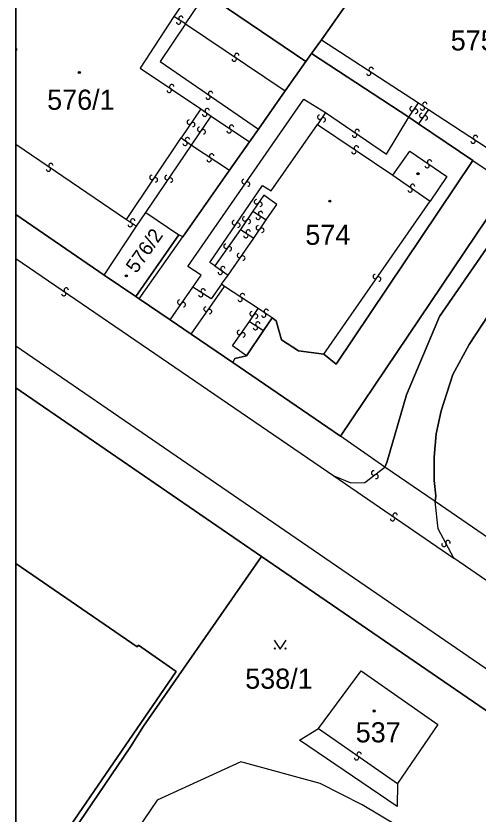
# Model space of a CAD drawing. Extents: x -600309 to -598967, y -1161267 to -1160292.
# Drawn here: x -600308.5 to -600269.6, y -1160535.7 to -1160468.5 of the extents above; entities that cross this region are included whole.
import ezdxf

# ---------------------------------------------------------------- set-up
doc = ezdxf.new("R2010")
doc.units = 0
for name, color, linetype in [('Level 1', 7, 'Continuous'), ('Level 13', 7, 'Continuous'), ('Level 3', 7, 'Continuous'), ('Level 4', 7, 'Continuous'), ('Level 5', 7, 'Continuous'), ('Level 60', 7, 'Continuous'), ('Vrstva 60', 7, 'Continuous'), ('Vrstva 63', 7, 'Continuous')]:
    doc.layers.add(name, color=color, linetype=linetype)

msp = doc.modelspace()

# ---------------------------------------------------------------- linework, layer by layer
at = {"layer": 'Level 1'}
for p, q in [((-600308.541, -1160485.2), (-600301.11, -1160490.31)), ((-600308.541, -1160499.81), (-600287.84, -1160514.02))]:
    msp.add_line(p, q, dxfattribs=at)
for points in [[(-600282.78, -1160470.49), (-600273.4, -1160457.1)], [(-600292.53, -1160466.58), (-600284.1, -1160472.3)], [(-600283.63, -1160471.64), (-600282.78, -1160470.49)], [(-600284.1, -1160472.3), (-600283.63, -1160471.64)], [(-600275.42, -1160477.01), (-600283.63, -1160471.64)], [(-600284.1, -1160472.3), (-600285.83, -1160474.79)], [(-600242.67, -1160473.81), (-600246.89, -1160473.4), (-600249.82, -1160473.65), (-600252.59, -1160474.29), (-600255.09, -1160475.12), (-600257.31, -1160476.17), (-600260.33, -1160477.98), (-600262.97, -1160480.2), (-600264.66, -1160481.97), (-600272.84, -1160493.8), (-600275.6, -1160500.4), (-600277.27, -1160506.1), (-600277.44, -1160506.49)], [(-600285.83, -1160474.79), (-600288.09, -1160478.01)], [(-600275.42, -1160477.01), (-600274.59, -1160477.56)], [(-600270.03, -1160480.64), (-600274.59, -1160477.56)], [(-600288.09, -1160478.01), (-600288.84, -1160479.08)], [(-600288.84, -1160479.08), (-600290.54, -1160481.48)], [(-600270.03, -1160480.64), (-600281.53, -1160497.81), (-600282.59, -1160496.99)], [(-600290.54, -1160481.48), (-600294.47, -1160487.08)], [(-600281.18, -1160503.89), (-600266.93, -1160482.72)], [(-600298.38, -1160486.2), (-600297.59, -1160485.05)], [(-600297.59, -1160485.05), (-600294.81, -1160486.92)], [(-600301.11, -1160490.31), (-600298.38, -1160486.2)], [(-600298.44, -1160492.13), (-600294.81, -1160486.92)], [(-600298.15, -1160492.32), (-600294.47, -1160487.08)], [(-600264.44, -1160487.2), (-600270.32, -1160496.15), (-600271.69, -1160498.68), (-600272.7, -1160501.74), (-600273.1, -1160503.69), (-600273.29, -1160505.66), (-600273.28, -1160507.64), (-600273.15, -1160508.93), (-600273.18, -1160509.41)], [(-600301.11, -1160490.31), (-600298.44, -1160492.13)], [(-600298.44, -1160492.13), (-600298.15, -1160492.32)], [(-600298.15, -1160492.32), (-600295.54, -1160494.09)], [(-600287.66, -1160494.97), (-600286.95, -1160493.92)], [(-600286.95, -1160493.92), (-600286.6, -1160494.17), (-600286.14, -1160495.77), (-600284.73, -1160496.71), (-600282.59, -1160496.99)], [(-600295.54, -1160494.09), (-600293.77, -1160495.29)], [(-600293.77, -1160495.29), (-600290.24, -1160497.67)], [(-600289.11, -1160497.13), (-600287.66, -1160494.97)], [(-600290.24, -1160497.67), (-600290.08, -1160497.34), (-600289.11, -1160497.13)], [(-600290.24, -1160497.67), (-600281.18, -1160503.89)], [(-600277.44, -1160506.49), (-600281.18, -1160503.89)], [(-600273.18, -1160509.41), (-600277.44, -1160506.49)], [(-600236.23, -1160534.79), (-600273.18, -1160509.41)], [(-600308.541, -1160544.31), (-600298.89, -1160530.07), (-600297.78, -1160528.33), (-600287.84, -1160514.02)], [(-600261.56, -1160532.05), (-600287.84, -1160514.02)], [(-600308.541, -1160514.629), (-600298.31, -1160521.66), (-600298.2, -1160521.51), (-600295.03, -1160523.73), (-600308.541, -1160543.415)], [(-600283.03, -1160528.54), (-600279.44, -1160523.67), (-600272.96, -1160528.19), (-600276.38, -1160533.16)], [(-600276.38, -1160533.16), (-600276.4, -1160535.11), (-600284.62, -1160529.5), (-600283.03, -1160528.54)]]:
    msp.add_lwpolyline(points, dxfattribs=at)
at = {"layer": 'Level 13'}
for centre, start, end in [((-600294.829, -1160468.976), 185.47258, 57.57058), ((-600294.632, -1160468.664), 5.25812, 237.84812), ((-600289.925, -1160471.808), 3.38499, 235.48298), ((-600290.134, -1160472.112), 183.17053, 55.76053), ((-600278.588, -1160472.986), 4.41531, 236.51331), ((-600278.791, -1160473.294), 184.20085, 56.79085), ((-600295.406, -1160474.428), 3.55374, 235.65174), ((-600295.613, -1160474.732), 183.33928, 55.92928), ((-600292.134, -1160475.009), 2.89352, 234.99151), ((-600292.345, -1160475.311), 182.67906, 55.26906), ((-600274.068, -1160475.927), 4.15748, 236.25548), ((-600292.412, -1160476.451), 1.8974, 233.9954), ((-600275.151, -1160476.294), 92.92454, 325.02254), ((-600274.849, -1160476.505), 272.71009, 145.30009), ((-600274.271, -1160476.234), 183.94303, 56.53303), ((-600292.627, -1160476.749), 181.68294, 54.27294), ((-600282.932, -1160477.007), 93.33619, 325.92619), ((-600282.628, -1160477.214), 273.55065, 145.64864), ((-600274.321, -1160476.854), 92.38932, 324.97932), ((-600274.019, -1160477.067), 272.60378, 144.70178), ((-600293.932, -1160477.416), 92.98719, 325.57719), ((-600293.628, -1160477.625), 273.20165, 145.29965), ((-600290.356, -1160477.848), 3.56041, 235.65841), ((-600293.052, -1160478.025), 93.30502, 325.40301), ((-600292.748, -1160478.234), 273.09056, 145.68056), ((-600290.563, -1160478.152), 183.34596, 55.93596), ((-600279.984, -1160478.512), 182.85408, 55.44408), ((-600279.775, -1160478.209), 3.06853, 235.16653), ((-600294.284, -1160479.202), 183.17211, 55.76211), ((-600294.075, -1160478.898), 3.38657, 235.48456), ((-600270.001, -1160479.024), 184.03787, 56.62787), ((-600269.798, -1160478.716), 4.25233, 236.35032), ((-600280.044, -1160479.902), 183.13582, 55.72582), ((-600279.835, -1160479.598), 3.35028, 235.44828), ((-600292.243, -1160480.573), 183.42678, 56.01678), ((-600292.036, -1160480.268), 3.64124, 235.73923), ((-600305.595, -1160481.078), 3.1643, 235.2623), ((-600273.874, -1160481.092), 182.83723, 55.42723), ((-600273.665, -1160480.789), 3.05168, 235.14968), ((-600305.804, -1160481.382), 182.94985, 55.53985), ((-600297.082, -1160482.076), 93.5098, 325.6078), ((-600296.778, -1160482.283), 273.29534, 145.88534), ((-600295.812, -1160482.095), 93.26715, 325.36515), ((-600295.508, -1160482.304), 273.0527, 145.6427), ((-600289.31, -1160482.433), 92.58042, 324.67842), ((-600289.009, -1160482.646), 272.36597, 144.95597), ((-600275.306, -1160483.14), 182.22734, 54.81734), ((-600275.093, -1160482.84), 2.4418, 234.53979), ((-600288.261, -1160484.135), 92.68606, 325.27606), ((-600287.959, -1160484.346), 272.90052, 144.99852), ((-600287.908, -1160485.127), 4.15326, 236.25126), ((-600298.904, -1160486.062), 182.85049, 55.44049), ((-600298.695, -1160485.759), 3.06494, 235.16294), ((-600290.131, -1160485.894), 92.9131, 325.01109), ((-600289.252, -1160485.576), 93.04381, 325.63381), ((-600288.948, -1160485.785), 273.25826, 145.35626), ((-600288.112, -1160485.434), 183.9388, 56.5288), ((-600289.829, -1160486.105), 272.69864, 145.28864), ((-600288.947, -1160486.687), 4.03203, 236.13002), ((-600288.113, -1160486.326), 93.68267, 325.78066), ((-600287.807, -1160486.533), 273.46821, 146.05821), ((-600289.152, -1160486.993), 183.81757, 56.40757), ((-600290.84, -1160487.884), 92.1914, 324.7814), ((-600290.54, -1160488.097), 272.40585, 144.50385), ((-600289.711, -1160488.663), 92.59145, 324.68945), ((-600289.409, -1160488.876), 272.37699, 144.96699), ((-600291.308, -1160490.069), 181.6206, 54.2106), ((-600291.091, -1160489.771), 1.83506, 233.93305), ((-600278.25, -1160490.433), 92.55996, 324.65796), ((-600277.949, -1160490.646), 272.3455, 144.9355), ((-600304.505, -1160491.881), 182.80285, 55.39285), ((-600304.295, -1160491.579), 3.01731, 235.1153), ((-600292.96, -1160491.965), 184.90154, 56.99954), ((-600292.761, -1160491.655), 4.68709, 237.27709), ((-600289.438, -1160492.047), 3.88778, 236.47778), ((-600294.731, -1160492.594), 92.78528, 324.88328), ((-600294.429, -1160492.805), 272.57082, 145.16082), ((-600289.643, -1160492.353), 184.10224, 56.20023), ((-600292.52, -1160493.173), 92.51485, 324.61285), ((-600292.219, -1160493.386), 272.30039, 144.89039), ((-600287.437, -1160493.377), 3.46821, 236.05821), ((-600288.632, -1160493.576), 93.43623, 325.53423), ((-600288.328, -1160493.783), 273.22178, 145.81178), ((-600287.644, -1160493.683), 183.68267, 55.78066), ((-600288.35, -1160494.744), 184.374, 56.964), ((-600288.149, -1160494.436), 4.58845, 236.68645), ((-600289.701, -1160495.144), 92.73519, 324.83319), ((-600289.399, -1160495.355), 272.52074, 145.11074), ((-600278.392, -1160506.993), 75.15371, 307.25171), ((-600278.168, -1160507.286), 254.93926, 127.52926), ((-600276.785, -1160510.851), 182.62569, 55.21569), ((-600276.574, -1160510.549), 2.84014, 234.93814), ((-600272.117, -1160512.855), 334.91682, 207.50682), ((-600272.444, -1160513.024), 155.13128, 27.22927), ((-600279.816, -1160531.001), 182.36914, 54.95914), ((-600279.603, -1160530.7), 2.5836, 234.6816)]:
    msp.add_arc(centre, 0.184, start, end, dxfattribs=at)
at = {"layer": 'Level 3'}
for p, q in [((-600308.541, -1160479.29), (-600299.23, -1160485.62)), ((-600308.541, -1160488.903), (-600281.73, -1160507.23)), ((-600308.541, -1160496.264), (-600187.53, -1160579.36))]:
    msp.add_line(p, q, dxfattribs=at)
for points in [[(-600293.48, -1160465.96), (-600295.22, -1160468.51)], [(-600294.24, -1160469.12), (-600292.53, -1160466.58)], [(-600295.22, -1160468.51), (-600298.07, -1160472.86), (-600292.95, -1160476.29)], [(-600294.24, -1160469.12), (-600295.22, -1160468.51)], [(-600294.24, -1160469.12), (-600296.39, -1160472.31), (-600288.09, -1160478.01)], [(-600294.24, -1160469.12), (-600285.83, -1160474.79)], [(-600282.78, -1160470.49), (-600274.59, -1160475.8)], [(-600308.541, -1160471.445), (-600308.43, -1160471.28), (-600308.541, -1160471.202)], [(-600293.63, -1160491.32), (-600292.93, -1160490.33), (-600294.06, -1160489.58), (-600284.27, -1160475.49), (-600282.44, -1160476.61)], [(-600275.42, -1160477.01), (-600274.59, -1160475.8)], [(-600274.59, -1160475.8), (-600273.75, -1160476.35)], [(-600292.95, -1160476.29), (-600294.62, -1160478.75)], [(-600292.95, -1160476.29), (-600292.08, -1160476.91)], [(-600273.75, -1160476.35), (-600274.59, -1160477.56)], [(-600273.75, -1160476.35), (-600266.04, -1160481.38)], [(-600293.73, -1160479.35), (-600292.08, -1160476.91)], [(-600292.08, -1160476.91), (-600288.84, -1160479.08)], [(-600282.44, -1160476.61), (-600283.11, -1160477.61)], [(-600282.44, -1160476.61), (-600277.31, -1160480.11), (-600275.42, -1160477.01)], [(-600291.76, -1160489.52), (-600292.2, -1160489.24), (-600287.76, -1160482.77), (-600287.01, -1160483.21), (-600283.11, -1160477.61)], [(-600283.11, -1160477.61), (-600276.77, -1160481.89)], [(-600299.23, -1160485.62), (-600294.62, -1160478.75)], [(-600294.62, -1160478.75), (-600293.73, -1160479.35)], [(-600297.59, -1160485.05), (-600293.73, -1160479.35)], [(-600293.73, -1160479.35), (-600290.54, -1160481.48)], [(-600276.77, -1160481.89), (-600275.33, -1160479.87), (-600272.21, -1160482), (-600273.62, -1160484.09)], [(-600270.03, -1160480.64), (-600266.93, -1160482.72)], [(-600276.77, -1160481.89), (-600273.62, -1160484.09)], [(-600287.44, -1160485.65), (-600286.53, -1160484.35), (-600287.65, -1160483.57), (-600288.57, -1160484.91)], [(-600282.59, -1160496.99), (-600273.62, -1160484.09)], [(-600288.57, -1160484.91), (-600289.62, -1160486.46)], [(-600288.57, -1160484.91), (-600287.44, -1160485.65)], [(-600299.23, -1160485.62), (-600298.38, -1160486.2)], [(-600288.48, -1160487.21), (-600287.44, -1160485.65)], [(-600289.62, -1160486.46), (-600291.76, -1160489.52)], [(-600289.62, -1160486.46), (-600288.48, -1160487.21)], [(-600294.47, -1160487.08), (-600294.81, -1160486.92)], [(-600290.64, -1160490.32), (-600288.48, -1160487.21)], [(-600291.76, -1160489.52), (-600290.64, -1160490.32)], [(-600291.2, -1160491.07), (-600290.64, -1160490.32)], [(-600293.77, -1160495.29), (-600290.97, -1160491.27)], [(-600291.2, -1160491.07), (-600292.09, -1160492.3), (-600293.63, -1160491.32)], [(-600290.97, -1160491.27), (-600291.2, -1160491.07)], [(-600288.12, -1160493.14), (-600290.97, -1160491.27)], [(-600295.54, -1160494.09), (-600293.63, -1160491.32)], [(-600288.84, -1160494.21), (-600288.12, -1160493.14)], [(-600286.95, -1160493.92), (-600288.12, -1160493.14)], [(-600289.11, -1160497.13), (-600290.27, -1160496.28), (-600288.84, -1160494.21)], [(-600288.84, -1160494.21), (-600287.66, -1160494.97)], [(-600281.73, -1160507.23), (-600280.29, -1160507.81), (-600279.13, -1160507.8), (-600277.44, -1160506.49)], [(-600281.73, -1160507.23), (-600271.63, -1160514.18)], [(-600271.63, -1160514.18), (-600272.93, -1160511.71), (-600273.18, -1160509.41)], [(-600127.43, -1160613.27), (-600144.18, -1160601.67), (-600151.61, -1160596.56), (-600155.1, -1160594.14), (-600271.63, -1160514.18)], [(-600283.03, -1160528.54), (-600276.38, -1160533.16)], [(-600268.06, -1160541.7), (-600270.01, -1160540.53), (-600279.36, -1160534.96), (-600282.9, -1160533.17), (-600289.58, -1160531.33), (-600296.63, -1160534.56), (-600303.69, -1160544.98), (-600305.81, -1160543.61), (-600308.541, -1160547.884)]]:
    msp.add_lwpolyline(points, dxfattribs=at)
at = {"layer": 'Level 5'}
msp.add_lwpolyline([(-600286.761, -1160521.09), (-600286.26, -1160521.84), (-600285.76, -1160521.09)], dxfattribs=at)
for centre, radius in [((-600303.2, -1160473.23), 0.09), ((-600303.2, -1160473.23), 0.0521), ((-600274.64, -1160481.77), 0.09), ((-600274.64, -1160481.77), 0.0521), ((-600282.08, -1160484.08), 0.09), ((-600282.08, -1160484.08), 0.0521), ((-600299.23, -1160490.37), 0.09), ((-600299.23, -1160490.37), 0.0521), ((-600286.71, -1160521.79), 0.05), ((-600285.811, -1160521.79), 0.05), ((-600278.33, -1160527.05), 0.09), ((-600278.33, -1160527.05), 0.0521)]:
    msp.add_circle(centre, radius, dxfattribs=at)
at = {"layer": 'Level 60'}
for points in [[(-600270.88, -1160453.48), (-600273.4, -1160457.1), (-600282.78, -1160470.49), (-600283.63, -1160471.64), (-600284.1, -1160472.3), (-600292.53, -1160466.58), (-600292.17, -1160466.07), (-600300.92, -1160460.12), (-600306.58, -1160456.31), (-600295.36, -1160440.08), (-600296.08, -1160439.52), (-600294.57, -1160437.35), (-600282.45, -1160445.53), (-600282.08, -1160445.78), (-600273.54, -1160451.65), (-600272.23, -1160452.57)], [(-600281.18, -1160503.89), (-600290.24, -1160497.67), (-600290.08, -1160497.34), (-600289.11, -1160497.13), (-600287.66, -1160494.97), (-600286.95, -1160493.92), (-600286.6, -1160494.17), (-600286.14, -1160495.77), (-600284.73, -1160496.71), (-600282.59, -1160496.99), (-600281.53, -1160497.81), (-600270.03, -1160480.64), (-600274.59, -1160477.56), (-600275.42, -1160477.01), (-600283.63, -1160471.64), (-600282.78, -1160470.49), (-600273.4, -1160457.1), (-600257.33, -1160468.55), (-600266.04, -1160481.38), (-600266.93, -1160482.72)], [(-600284.1, -1160472.3), (-600283.63, -1160471.64), (-600275.42, -1160477.01), (-600274.59, -1160477.56), (-600270.03, -1160480.64), (-600281.53, -1160497.81), (-600282.59, -1160496.99), (-600284.73, -1160496.71), (-600286.14, -1160495.77), (-600286.6, -1160494.17), (-600286.95, -1160493.92), (-600287.66, -1160494.97), (-600289.11, -1160497.13), (-600290.08, -1160497.34), (-600290.24, -1160497.67), (-600293.77, -1160495.29), (-600295.54, -1160494.09), (-600298.15, -1160492.32), (-600294.47, -1160487.08), (-600290.54, -1160481.48), (-600288.84, -1160479.08), (-600288.09, -1160478.01), (-600285.83, -1160474.79)], [(-600298.44, -1160492.13), (-600301.11, -1160490.31), (-600298.38, -1160486.2), (-600297.59, -1160485.05), (-600294.81, -1160486.92)], [(-600279.44, -1160523.67), (-600272.96, -1160528.19), (-600276.38, -1160533.16), (-600276.4, -1160535.11), (-600284.62, -1160529.5), (-600283.03, -1160528.54)]]:
    msp.add_lwpolyline(points, close=True, dxfattribs=at)
for points in [[(-600264.66, -1160481.97), (-600272.84, -1160493.8), (-600275.6, -1160500.4), (-600277.27, -1160506.1), (-600277.44, -1160506.49), (-600281.18, -1160503.89), (-600266.93, -1160482.72)], [(-600264.44, -1160487.2), (-600270.32, -1160496.15), (-600271.69, -1160498.68), (-600272.7, -1160501.74), (-600273.1, -1160503.69), (-600273.29, -1160505.66), (-600273.28, -1160507.64), (-600273.15, -1160508.93), (-600273.18, -1160509.41), (-600277.44, -1160506.49), (-600277.27, -1160506.1), (-600275.6, -1160500.4), (-600272.84, -1160493.8), (-600264.66, -1160481.97)], [(-600236.23, -1160534.79), (-600273.18, -1160509.41), (-600273.15, -1160508.93), (-600273.28, -1160507.64), (-600273.29, -1160505.66), (-600273.1, -1160503.69), (-600272.7, -1160501.74), (-600271.69, -1160498.68), (-600270.32, -1160496.15), (-600264.44, -1160487.2)]]:
    msp.add_lwpolyline(points, dxfattribs=at)
at = {"layer": 'Vrstva 60'}
for points in [[(-600308.541, -1160459.142), (-600308.541, -1160485.2), (-600301.11, -1160490.31), (-600298.38, -1160486.2), (-600297.59, -1160485.05), (-600294.81, -1160486.92), (-600298.44, -1160492.13), (-600298.15, -1160492.32), (-600294.47, -1160487.08), (-600290.54, -1160481.48), (-600288.84, -1160479.08), (-600288.09, -1160478.01), (-600285.83, -1160474.79), (-600284.1, -1160472.3), (-600292.53, -1160466.58), (-600292.17, -1160466.07), (-600300.92, -1160460.12), (-600306.58, -1160456.31)], [(-600308.541, -1160499.81), (-600308.541, -1160514.629), (-600298.31, -1160521.66), (-600298.2, -1160521.51), (-600295.03, -1160523.73), (-600308.541, -1160543.415), (-600308.541, -1160544.31), (-600298.89, -1160530.07), (-600297.78, -1160528.33), (-600287.84, -1160514.02)], [(-600308.541, -1160514.629), (-600308.541, -1160543.415), (-600295.03, -1160523.73), (-600298.2, -1160521.51), (-600298.31, -1160521.66)], [(-600276.38, -1160533.16), (-600276.4, -1160535.11), (-600284.62, -1160529.5), (-600283.03, -1160528.54), (-600279.44, -1160523.67), (-600272.96, -1160528.19)]]:
    msp.add_lwpolyline(points, close=True, dxfattribs=at)
for points in [[(-600226.4, -1160541.57), (-600234.92, -1160535.66), (-600236.23, -1160534.79), (-600273.18, -1160509.41), (-600277.44, -1160506.49), (-600281.18, -1160503.89), (-600290.24, -1160497.67), (-600293.77, -1160495.29), (-600295.54, -1160494.09), (-600298.15, -1160492.32), (-600298.44, -1160492.13), (-600301.11, -1160490.31), (-600308.541, -1160485.2), (-600308.541, -1160499.81), (-600287.84, -1160514.02), (-600261.56, -1160532.05), (-600240.68, -1160546.53)], [(-600268.06, -1160541.7), (-600261.81, -1160532.42), (-600261.56, -1160532.05), (-600287.84, -1160514.02), (-600297.78, -1160528.33), (-600298.89, -1160530.07), (-600308.541, -1160544.31)]]:
    msp.add_lwpolyline(points, dxfattribs=at)
at = {"layer": 'Vrstva 63'}
msp.add_lwpolyline([(-600308.541, -1160292.347), (-598967.108, -1160292.347), (-598967.108, -1161267.031), (-600308.541, -1161267.031)], close=True, dxfattribs=at)

# ---------------------------------------------------------------- texts
at = {"layer": 'Level 4'}
for s, p in [('575', (-600271.88, -1160471.38)), ('576/1', (-600305.91, -1160476.38)), ('574', (-600284.14, -1160487.76)), ('538/1', (-600289.21, -1160525.18)), ('537', (-600279.89, -1160529.7))]:
    msp.add_text(s, height=1.7, dxfattribs=at).set_placement(p)
msp.add_text('576/2', height=1.2, rotation=54.9, dxfattribs=at).set_placement((-600298.39, -1160490.23))

doc.saveas('drawing.dxf')
